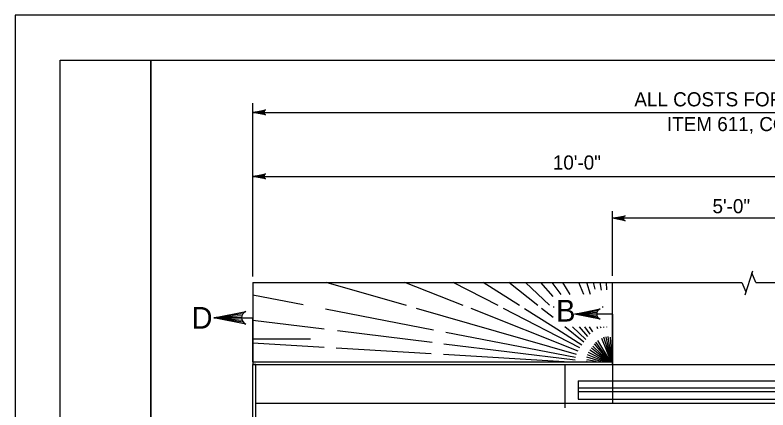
# Model space of a CAD drawing. Extents: x 0 to 34, y 0 to 22.
# Drawn here: x 0 to 8.32, y 17.63 to 22 of the extents above; entities that cross this region are included whole.
import ezdxf

# ---------------------------------------------------------------- set-up
doc = ezdxf.new("R2010")
doc.units = 0
for name, color, linetype in [('Default', 7, 'Continuous'), ('SH_Border', 7, 'Continuous'), ('SH_Cut_Line', 7, 'Continuous')]:
    doc.layers.add(name, color=color, linetype=linetype)

msp = doc.modelspace()

# ---------------------------------------------------------------- linework, layer by layer
at = {"layer": 'Default'}
for p, q in [((2.6287, 19.1091), (2.6287, 21.0265)), ((2.7568, 20.9423), (2.6287, 20.9244)), ((2.7525, 20.9335), (2.6287, 20.9244)), ((2.6287, 20.9244), (18.4715, 20.9244)), ((2.7512, 20.9244), (2.6287, 20.9244)), ((2.7534, 20.9129), (2.6287, 20.9244)), ((2.7583, 20.9045), (2.6287, 20.9244)), ((2.7568, 20.2343), (2.6287, 20.2164)), ((2.7525, 20.2255), (2.6287, 20.2164)), ((2.6287, 20.2164), (18.4715, 20.2164)), ((2.7512, 20.2164), (2.6287, 20.2164)), ((2.7534, 20.2049), (2.6287, 20.2164)), ((2.7583, 20.1965), (2.6287, 20.2164)), ((6.6032, 19.1185), (6.6032, 19.8318)), ((6.7314, 19.7711), (6.6032, 19.7531)), ((6.7271, 19.7622), (6.6032, 19.7531)), ((14.532, 19.7531), (6.6032, 19.7531)), ((6.7257, 19.7531), (6.6032, 19.7531)), ((6.7281, 19.7416), (6.6032, 19.7531)), ((6.733, 19.7334), (6.6032, 19.7531)), ((8.1529, 19.1702), (8.066, 18.9031)), ((8.1883, 19.0451), (8.146, 19.1489)), ((2.6287, 19.0451), (8.0355, 19.0451)), ((2.6287, 19.0451), (2.6299, 18.1355)), ((4.3259, 18.79), (3.4379, 19.0451)), ((4.9546, 18.7895), (4.3098, 19.0451)), ((5.3392, 18.7889), (4.8431, 19.0451)), ((5.5748, 18.7912), (5.1764, 19.0451)), ((5.778, 18.7908), (5.4576, 19.0451)), ((5.9091, 18.7929), (5.6427, 19.0451)), ((5.9476, 18.8904), (5.813, 19.0451)), ((6.0365, 18.911), (5.9384, 19.0451)), ((6.1354, 18.911), (6.0545, 19.0451)), ((6.2886, 18.911), (6.2341, 19.0451)), ((6.3617, 18.911), (6.3199, 19.0451)), ((6.4129, 18.9696), (6.3956, 19.0451)), ((6.4813, 18.9604), (6.4687, 19.0451)), ((6.5428, 18.9635), (6.5368, 19.0451)), ((6.6032, 18.1722), (6.6032, 19.0451)), ((8.0355, 19.0451), (8.0783, 18.9411)), ((8.1883, 19.0451), (12.9905, 19.0451)), ((3.1848, 18.7951), (2.6288, 18.9024)), ((4.6272, 18.5169), (3.4329, 18.7473)), ((6.2071, 18.2495), (4.4377, 18.7579)), ((6.2232, 18.2863), (5.0407, 18.7553)), ((6.2416, 18.3225), (5.4007, 18.757)), ((5.9476, 18.5535), (5.6332, 18.754)), ((5.9476, 18.6561), (5.8207, 18.7569)), ((5.9476, 18.7761), (5.958, 18.7761)), ((6.4414, 18.7311), (6.1851, 18.6952)), ((6.4918, 18.7761), (6.5, 18.7761)), ((2.5177, 18.6982), (2.1972, 18.6534)), ((2.5069, 18.6761), (2.1972, 18.6534)), ((2.1972, 18.6534), (2.6299, 18.6534)), ((2.5036, 18.6534), (2.1972, 18.6534)), ((2.5092, 18.6246), (2.1972, 18.6534)), ((2.5216, 18.6038), (2.1972, 18.6534)), ((2.6299, 18.167), (2.6299, 18.6534)), ((6.4327, 18.7134), (6.1851, 18.6952)), ((6.4301, 18.6952), (6.1851, 18.6952)), ((6.4347, 18.6722), (6.1851, 18.6952)), ((6.4445, 18.6556), (6.1851, 18.6952)), ((6.5, 18.6952), (6.4113, 18.6952)), ((6.6032, 18.6952), (6.5, 18.6952)), ((6.6032, 18.6952), (6.6032, 18.1722)), ((6.6032, 18.6952), (6.6032, 18.1722)), ((3.4177, 18.526), (2.6292, 18.6225)), ((4.6124, 18.3795), (3.5651, 18.5079)), ((6.1962, 18.2141), (4.7617, 18.4909)), ((6.2652, 18.351), (5.9496, 18.5522)), ((6.2882, 18.3857), (6.0784, 18.5522)), ((6.3109, 18.4124), (6.1632, 18.5522)), ((6.3327, 18.447), (6.2412, 18.5522)), ((6.3571, 18.4724), (6.2987, 18.5522)), ((6.3855, 18.4965), (6.3519, 18.5522)), ((6.443, 18.5305), (6.4342, 18.5522)), ((6.4774, 18.5396), (6.4734, 18.5522)), ((6.5093, 18.5472), (6.5082, 18.5522)), ((6.5419, 18.5503), (6.5417, 18.5522)), ((2.6291, 18.4219), (3.2642, 18.4219)), ((6.5812, 18.172), (6.4432, 18.401)), ((6.5884, 18.172), (6.4853, 18.4261)), ((6.5919, 18.172), (6.5086, 18.4396)), ((6.5949, 18.1721), (6.5329, 18.4439)), ((6.5978, 18.1721), (6.5574, 18.4457)), ((6.6006, 18.1721), (6.5811, 18.4397)), ((3.4177, 18.3245), (2.6296, 18.3713)), ((4.6008, 18.2544), (3.5512, 18.3165)), ((6.1933, 18.1858), (4.7403, 18.3638)), ((6.5577, 18.1717), (6.3717, 18.3195)), ((6.565, 18.1718), (6.3866, 18.3407)), ((6.5717, 18.1719), (6.4037, 18.3652)), ((6.5767, 18.172), (6.4213, 18.3845)), ((6.0704, 18.1672), (4.7347, 18.2464)), ((6.513, 18.1713), (6.3288, 18.2444)), ((6.5337, 18.1715), (6.3404, 18.2714)), ((6.5467, 18.1716), (6.3537, 18.2946)), ((2.6299, 18.167), (6.6032, 18.167)), ((6.3257, 18.1695), (6.3188, 18.1704)), ((6.4223, 18.1705), (6.3208, 18.19)), ((6.4799, 18.171), (6.3212, 18.2166)), ((6.6032, 18.1355), (6.6032, 18.1722)), ((6.6032, 18.1722), (6.6032, 17.7115)), ((2.6299, 14.754), (2.6299, 18.1355)), ((2.6299, 18.1355), (2.6587, 18.1355)), ((2.6619, 18.1355), (2.6331, 18.1355)), ((2.6587, 18.1355), (6.6032, 18.1355)), ((2.6619, 14.754), (2.6619, 18.1355)), ((6.0797, 17.6715), (6.0797, 18.1355)), ((6.6032, 18.1355), (13.4872, 18.1355)), ((6.6032, 18.1355), (6.6032, 17.7115)), ((6.2257, 17.9577), (13.2226, 17.9577)), ((6.2257, 17.9577), (6.2257, 17.7539)), ((6.2257, 17.8798), (13.2226, 17.8798)), ((6.2257, 17.8384), (13.2226, 17.8384)), ((6.2257, 17.7539), (13.2226, 17.7539)), ((2.6667, 17.7115), (13.2226, 17.7115)), ((6.0797, 17.6579), (6.0797, 17.6715))]:
    msp.add_line(p, q, dxfattribs=at)
for points in [[(2.7702, 20.896), (2.6287, 20.9244), (2.7702, 20.9527)], [(2.7702, 20.188), (2.6287, 20.2164), (2.7702, 20.2447)], [(6.7448, 19.7249), (6.6032, 19.7531), (6.7448, 19.7815)], [(6.4682, 18.6386), (6.1851, 18.6952), (6.4682, 18.7519)], [(2.5512, 18.5826), (2.1972, 18.6534), (2.5512, 18.7242)]]:
    msp.add_lwpolyline(points, dxfattribs=at)
for centre, radius in [((2.7817, 20.9244), 0.0306), ((2.7817, 20.2164), 0.0306), ((6.7563, 19.7532), 0.0306), ((6.4911, 18.6953), 0.0611), ((2.5799, 18.6535), 0.0764)]:
    msp.add_arc(centre, radius, 112.08782, 247.91395, dxfattribs=at)
at = {"layer": 'SH_Border'}
for points in [[(0.5, 21.5), (1.5, 21.5), (1.5, 0.5), (0.5, 0.5)], [(1.5, 21.5), (33.5, 21.5), (33.5, 0.5), (1.5, 0.5)]]:
    msp.add_lwpolyline(points, close=True, dxfattribs=at)
at = {"layer": 'SH_Cut_Line'}
msp.add_lwpolyline([(0, 0), (34, 0), (34, 22), (0, 22)], close=True, dxfattribs=at)

# ---------------------------------------------------------------- texts
at = {"layer": 'Default'}
for s, height, p in [('ALL COSTS FOR CONCRETE BARRIER AND INLET ARE INCLUDED IN ', 0.156, (6.846, 20.9907)), ('ITEM 611, CONCRETE BARRIER (TYPE D) INLET, AS PER PLAN', 0.156, (7.2063, 20.7167)), ('10\'-0" ', 0.156, (5.9448, 20.292)), ('5\'-0" ', 0.156, (7.7102, 19.8095)), ('B', 0.24, (5.9809, 18.612)), ('D', 0.24, (1.9512, 18.5331))]:
    msp.add_text(s, height=height, dxfattribs=at).set_placement(p)

doc.saveas('drawing.dxf')
